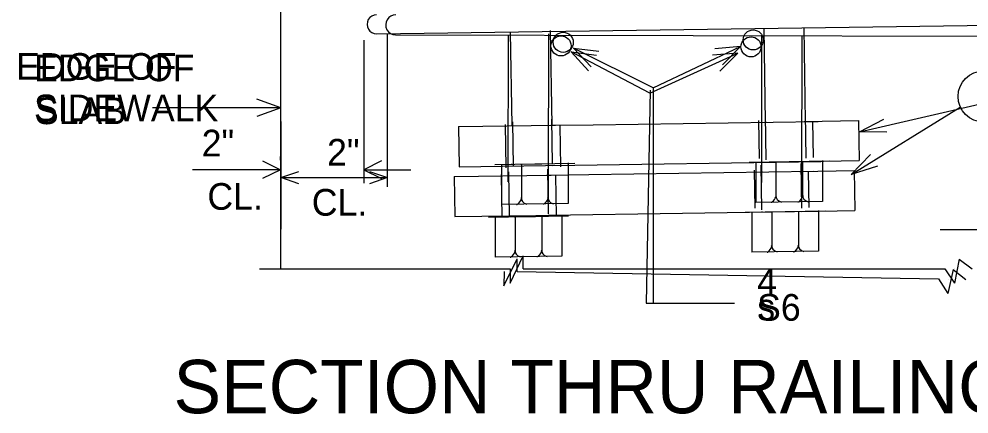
# Model space of a CAD drawing. Extents: x 1509.2 to 1521.3, y 1506 to 1514.6.
# Drawn here: x 1510.473 to 1511.957, y 1509.298 to 1509.914 of the extents above; entities that cross this region are included whole.
import ezdxf

# ---------------------------------------------------------------- set-up
doc = ezdxf.new("R2010")
doc.units = 0
for name, color, linetype in [('Level 2', 7, 'Continuous'), ('Level 3', 7, 'Continuous'), ('Level 4', 7, 'Continuous'), ('Level 60', 7, 'Continuous')]:
    doc.layers.add(name, color=color, linetype=linetype)

msp = doc.modelspace()

# ---------------------------------------------------------------- linework, layer by layer
at = {"layer": 'Level 3'}
for p, q in [((1510.8824, 1509.5244), (1510.8824, 1510.013)), ((1511.0322, 1509.8914), (1512.445, 1509.9114)), ((1511.3033, 1509.8964), (1511.3056, 1509.7486)), ((1511.6367, 1509.9001), (1511.6389, 1509.7533)), ((1511.6993, 1509.9001), (1511.7014, 1509.7545)), ((1511.0118, 1509.8816), (1511.0118, 1509.6582)), ((1511.2408, 1509.8933), (1511.243, 1509.7486)), ((1511.4638, 1509.8068), (1511.3395, 1509.869)), ((1511.3395, 1509.869), (1511.367, 1509.8399)), ((1511.3395, 1509.869), (1511.3793, 1509.8644)), ((1511.4638, 1509.8068), (1511.6002, 1509.8714)), ((1511.6002, 1509.8714), (1511.5603, 1509.8677)), ((1511.6002, 1509.8714), (1511.5721, 1509.843)), ((1511.4638, 1509.8068), (1511.4638, 1509.4698)), ((1510.8824, 1509.7758), (1510.6818, 1509.7758)), ((1510.8824, 1509.7758), (1510.8448, 1509.7894)), ((1510.8824, 1509.7758), (1510.8448, 1509.7621)), ((1511.7863, 1509.7384), (1511.98, 1509.7828)), ((1511.6389, 1509.7643), (1511.64, 1509.6944)), ((1511.7013, 1509.7669), (1511.7023, 1509.6971)), ((1510.8824, 1509.7543), (1510.8824, 1509.5863)), ((1511.1598, 1509.7463), (1511.3112, 1509.7484)), ((1511.1598, 1509.7463), (1511.1608, 1509.6838)), ((1511.2328, 1509.7495), (1511.2338, 1509.6821)), ((1511.2443, 1509.7539), (1511.2453, 1509.6841)), ((1511.304, 1509.7484), (1511.3058, 1509.7484)), ((1511.3053, 1509.7578), (1511.3063, 1509.688)), ((1511.3056, 1509.7484), (1511.37, 1509.7493)), ((1511.3196, 1509.6837), (1511.3186, 1509.7483)), ((1511.37, 1509.7493), (1511.7217, 1509.7546)), ((1511.6299, 1509.6967), (1511.629, 1509.756)), ((1511.639, 1509.7535), (1511.6412, 1509.7535)), ((1511.6998, 1509.7544), (1511.7848, 1509.7557)), ((1511.6998, 1509.7544), (1511.7016, 1509.7544)), ((1511.7143, 1509.6979), (1511.7134, 1509.7547)), ((1511.7848, 1509.7557), (1511.7857, 1509.6932)), ((1510.8816, 1509.6938), (1510.8816, 1509.6998)), ((1511.1608, 1509.6838), (1511.3295, 1509.6862)), ((1511.3414, 1509.6888), (1511.2164, 1509.6869)), ((1511.2268, 1509.6865), (1511.2268, 1509.6246)), ((1511.2422, 1509.6876), (1511.2435, 1509.6876)), ((1511.2568, 1509.6878), (1511.2899, 1509.6883)), ((1511.2582, 1509.6881), (1511.2582, 1509.6351)), ((1511.2998, 1509.6887), (1511.2998, 1509.634)), ((1511.3044, 1509.6885), (1511.3047, 1509.6885)), ((1511.3065, 1509.6859), (1511.7262, 1509.6921)), ((1511.3311, 1509.6898), (1511.3311, 1509.6262)), ((1511.7392, 1509.6923), (1511.6142, 1509.6903)), ((1511.6246, 1509.6899), (1511.6246, 1509.628)), ((1511.6399, 1509.691), (1511.6413, 1509.691)), ((1511.6546, 1509.6913), (1511.6877, 1509.6918)), ((1511.6559, 1509.6915), (1511.6559, 1509.6385)), ((1511.6975, 1509.6921), (1511.6975, 1509.6374)), ((1511.7022, 1509.6919), (1511.7857, 1509.6932)), ((1511.7022, 1509.6919), (1511.7024, 1509.6919)), ((1511.7288, 1509.6932), (1511.7288, 1509.6296)), ((1510.8816, 1509.679), (1510.7441, 1509.679)), ((1511.0118, 1509.679), (1511.0853, 1509.679)), ((1511.7288, 1509.6296), (1511.6246, 1509.628)), ((1511.3311, 1509.6262), (1511.2268, 1509.6246)), ((1511.2408, 1509.5018), (1511.2609, 1509.5445)), ((1511.2609, 1509.5244), (1511.2609, 1509.5445)), ((1511.9423, 1509.5395), (1511.9347, 1509.5018)), ((1511.9423, 1509.5395), (1511.9623, 1509.5244)), ((1510.8487, 1509.5244), (1511.2408, 1509.5244)), ((1511.2408, 1509.5244), (1511.2408, 1509.5018)), ((1511.2609, 1509.5244), (1511.9196, 1509.5244)), ((1511.9196, 1509.5244), (1511.9347, 1509.5018)), ((1511.9347, 1509.5244), (1511.9347, 1509.5244)), ((1511.4679, 1509.4706), (1511.59, 1509.4706))]:
    msp.add_line(p, q, dxfattribs=at)
for points in [[(1511.8293, 1509.7376), (1511.7863, 1509.7384), (1511.8246, 1509.7578)], [(1510.8538, 1509.6929), (1510.8816, 1509.679), (1510.8538, 1509.6651)], [(1511.0395, 1509.6929), (1511.0118, 1509.679), (1511.0395, 1509.6651)]]:
    msp.add_lwpolyline(points, dxfattribs=at)
for centre in [(1511.6203, 1509.8817), (1511.3235, 1509.878)]:
    msp.add_circle(centre, 0.0157, dxfattribs=at)
msp.add_arc((1511.0318, 1509.9062), 0.0148, 90.3237, 271.1515, dxfattribs=at)
for centre, major_axis, ratio, start_param, end_param in [((1511.2543, 1509.63), (0.00363, 0.00504), 0.295973, 3.141593, 6.283185), ((1511.2686, 1509.6319), (-0.0104, 0.0031), 0.648879, 0, 1.570796), ((1511.2959, 1509.6306), (0.00363, 0.00504), 0.295973, 3.141593, 6.283185), ((1511.3102, 1509.6325), (-0.0104, 0.0031), 0.648879, 0, 1.570796), ((1511.652, 1509.6335), (0.00363, 0.00504), 0.295973, 3.141593, 6.283185), ((1511.6663, 1509.6353), (-0.0104, 0.0031), 0.648879, 0, 1.570796), ((1511.6936, 1509.634), (0.00363, 0.00504), 0.295973, 3.141593, 6.283185), ((1511.708, 1509.6359), (-0.0104, 0.0031), 0.648879, 0, 1.570796)]:
    msp.add_ellipse(centre, major_axis=major_axis, ratio=ratio, start_param=start_param, end_param=end_param, dxfattribs=at)
at = {"layer": 'Level 4'}
for p, q in [((1510.8824, 1509.5244), (1510.8824, 1510.013)), ((1511.0491, 1509.6522), (1511.0491, 1509.8913)), ((1511.0614, 1509.8897), (1512.4419, 1509.8863)), ((1511.2376, 1509.8891), (1511.2371, 1509.66)), ((1511.3002, 1509.8912), (1511.2997, 1509.6598)), ((1511.6335, 1509.8891), (1511.633, 1509.6591)), ((1511.6961, 1509.8878), (1511.6955, 1509.6589)), ((1511.459, 1509.7988), (1511.3358, 1509.8632)), ((1511.3358, 1509.8632), (1511.3628, 1509.8336)), ((1511.3358, 1509.8632), (1511.3755, 1509.8579)), ((1511.459, 1509.7988), (1511.5965, 1509.861)), ((1511.5965, 1509.861), (1511.5566, 1509.858)), ((1511.5965, 1509.861), (1511.568, 1509.8331)), ((1511.4592, 1509.8034), (1511.4533, 1509.4708)), ((1510.8824, 1509.7758), (1510.7839, 1509.7758)), ((1510.8824, 1509.7758), (1510.8448, 1509.7894)), ((1510.8824, 1509.7758), (1510.8448, 1509.7621)), ((1511.7734, 1509.6718), (1511.9437, 1509.7767)), ((1510.8824, 1509.7543), (1510.8824, 1509.5863)), ((1511.6324, 1509.6863), (1511.6335, 1509.6165)), ((1511.6948, 1509.689), (1511.6958, 1509.6192)), ((1511.2263, 1509.6716), (1511.2273, 1509.6042)), ((1511.2378, 1509.676), (1511.2388, 1509.6062)), ((1511.2988, 1509.6799), (1511.2998, 1509.6101)), ((1511.2991, 1509.6705), (1511.3635, 1509.6714)), ((1511.3635, 1509.6714), (1511.7152, 1509.6767)), ((1511.6234, 1509.6188), (1511.6225, 1509.6781)), ((1511.6325, 1509.6756), (1511.6347, 1509.6756)), ((1511.6933, 1509.6765), (1511.7783, 1509.6778)), ((1511.6933, 1509.6765), (1511.6951, 1509.6765)), ((1511.7078, 1509.62), (1511.7069, 1509.6768)), ((1511.7783, 1509.6778), (1511.7792, 1509.6153)), ((1510.8824, 1509.6668), (1511.0491, 1509.6668)), ((1511.1533, 1509.6684), (1511.3047, 1509.6705)), ((1511.1533, 1509.6684), (1511.1543, 1509.6059)), ((1511.2975, 1509.6705), (1511.2993, 1509.6705)), ((1511.3131, 1509.6058), (1511.3121, 1509.6704)), ((1511.3, 1509.608), (1511.7197, 1509.6142)), ((1511.7327, 1509.6143), (1511.6077, 1509.6124)), ((1511.6181, 1509.612), (1511.6181, 1509.5501)), ((1511.6334, 1509.6131), (1511.6348, 1509.6131)), ((1511.6481, 1509.6133), (1511.6812, 1509.6138)), ((1511.6494, 1509.6136), (1511.6494, 1509.5606)), ((1511.691, 1509.6142), (1511.691, 1509.5595)), ((1511.6957, 1509.614), (1511.7792, 1509.6153)), ((1511.6957, 1509.614), (1511.6959, 1509.614)), ((1511.7223, 1509.6153), (1511.7223, 1509.5517)), ((1511.1543, 1509.6059), (1511.323, 1509.6083)), ((1511.3315, 1509.6066), (1511.2065, 1509.6047)), ((1511.2169, 1509.6043), (1511.2169, 1509.5423)), ((1511.2323, 1509.6053), (1511.2336, 1509.6053)), ((1511.2469, 1509.6056), (1511.28, 1509.6061)), ((1511.2483, 1509.6058), (1511.2483, 1509.5528)), ((1511.2898, 1509.6064), (1511.2898, 1509.5518)), ((1511.2945, 1509.6063), (1511.2948, 1509.6063)), ((1511.3212, 1509.6075), (1511.3212, 1509.5439)), ((1512.4083, 1509.585), (1511.9123, 1509.585)), ((1511.3212, 1509.5439), (1511.2169, 1509.5423)), ((1511.2308, 1509.4977), (1511.2516, 1509.5401)), ((1511.2513, 1509.52), (1511.2516, 1509.5401)), ((1511.7223, 1509.5517), (1511.6181, 1509.5501)), ((1510.8487, 1509.5244), (1511.2408, 1509.5244)), ((1511.9328, 1509.5232), (1511.9245, 1509.4856)), ((1511.9328, 1509.5232), (1511.9526, 1509.5078)), ((1511.2312, 1509.5203), (1511.2308, 1509.4977)), ((1511.2513, 1509.52), (1511.9098, 1509.5085)), ((1511.9098, 1509.5085), (1511.9245, 1509.4856)), ((1511.925, 1509.5083), (1511.925, 1509.5083)), ((1511.4533, 1509.4708), (1511.591, 1509.4708))]:
    msp.add_line(p, q, dxfattribs=at)
for points in [[(1511.8143, 1509.6848), (1511.7734, 1509.6718), (1511.8034, 1509.7026)], [(1510.9106, 1509.657), (1510.8824, 1509.6668), (1510.9106, 1509.6765)], [(1511.0208, 1509.6765), (1511.049, 1509.6667), (1511.0208, 1509.657)]]:
    msp.add_lwpolyline(points, dxfattribs=at)
for centre, radius in [((1511.32, 1509.8724), 0.0157), ((1511.6169, 1509.8709), 0.0157), ((1511.9805, 1509.7934), 0.04)]:
    msp.add_circle(centre, radius, dxfattribs=at)
msp.add_arc((1511.0617, 1509.9053), 0.0156, 88.8702, 269.1445, dxfattribs=at)
for centre, major_axis, ratio, start_param, end_param in [((1511.2444, 1509.5478), (0.00363, 0.00504), 0.295973, 3.141593, 6.283185), ((1511.2587, 1509.5497), (-0.0104, 0.0031), 0.648879, 0, 1.570796), ((1511.286, 1509.5484), (0.00363, 0.00504), 0.295973, 3.141593, 6.283185), ((1511.3003, 1509.5503), (-0.0104, 0.0031), 0.648879, 0, 1.570796), ((1511.6455, 1509.5555), (0.00363, 0.00504), 0.295973, 3.141593, 6.283185), ((1511.6598, 1509.5574), (-0.0104, 0.0031), 0.648879, 0, 1.570796), ((1511.6871, 1509.5561), (0.00363, 0.00504), 0.295973, 3.141593, 6.283185), ((1511.7015, 1509.558), (-0.0104, 0.0031), 0.648879, 0, 1.570796)]:
    msp.add_ellipse(centre, major_axis=major_axis, ratio=ratio, start_param=start_param, end_param=end_param, dxfattribs=at)

# ---------------------------------------------------------------- texts
at = {"layer": 'Level 2'}
msp.add_text('SECTION THRU RAILING ON', height=0.083334, rotation=0, dxfattribs=at).set_placement((1510.7146, 1509.2988))
at = {"layer": 'Level 3'}
for s, p in [('EDGE OF', (1510.4686, 1509.8195)), ('SLAB', (1510.4979, 1509.7502))]:
    msp.add_text(s, height=0.04167, rotation=0, dxfattribs=at).set_placement(p)
for s, p in [(' 2" ', (1510.7431, 1509.6998)), ('CL.', (1510.7675, 1509.6165)), ('S6  ', (1511.6263, 1509.4433))]:
    msp.add_text(s, height=0.04167, dxfattribs=at).set_placement(p)
at = {"layer": 'Level 4'}
for s, p in [('EDGE OF', (1510.4966, 1509.8172)), ('SIDEWALK', (1510.4966, 1509.7547))]:
    msp.add_text(s, height=0.04167, rotation=0, dxfattribs=at).set_placement(p)
for s, p in [('2"', (1510.9545, 1509.6855)), ('CL.', (1510.9306, 1509.6073)), ('s   ', (1511.6267, 1509.444))]:
    msp.add_text(s, height=0.04167, dxfattribs=at).set_placement(p)
at = {"layer": 'Level 60'}
msp.add_text('4', height=0.0417, dxfattribs=at).set_placement((1511.6263, 1509.4833))

doc.saveas('drawing.dxf')
